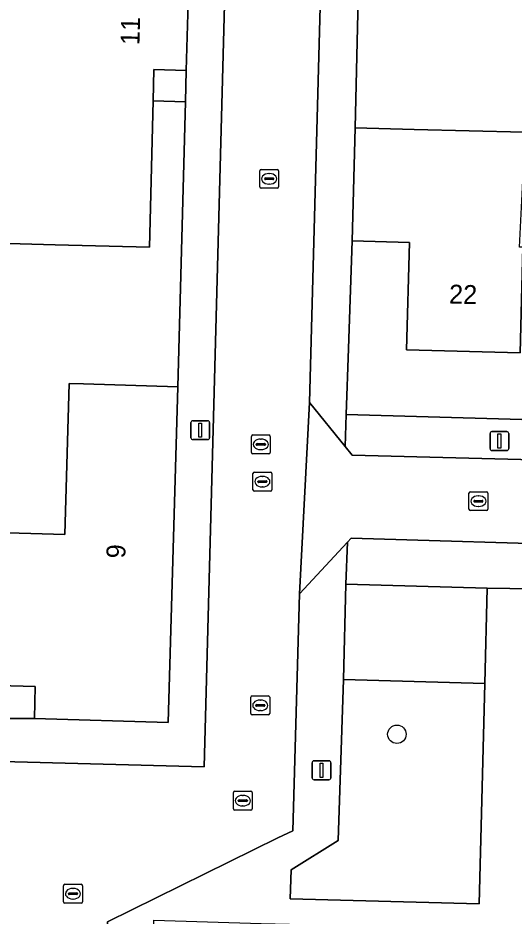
# Model space of a CAD drawing. Extents: x 162082 to 163401, y 388089 to 388636.
# Drawn here: x 162269.46 to 162295.76, y 388373.48 to 388421.05 of the extents above; entities that cross this region are included whole.
import ezdxf

# ---------------------------------------------------------------- set-up
doc = ezdxf.new("R2010")
doc.units = 0
for name, color, linetype in [('IMGEO_Boom', 7, 'Continuous'), ('IMGEO_Erf', 7, 'Continuous'), ('IMGEO_Groenvoorziening', 7, 'Continuous'), ('IMGEO_Kolk', 7, 'Continuous'), ('IMGEO_Lichtmast', 7, 'Continuous'), ('IMGEO_Pand', 7, 'Continuous'), ('IMGEO_Pand_nummerreeks', 7, 'Continuous'), ('IMGEO_Parkeervlak_open', 7, 'Continuous'), ('IMGEO_Rijbaan_lokaal_open', 7, 'Continuous'), ('IMGEO_Rioolput', 7, 'Continuous'), ('IMGEO_Voetpad_open', 7, 'Continuous')]:
    doc.layers.add(name, color=color, linetype=linetype)

msp = doc.modelspace()

# ---------------------------------------------------------------- linework, layer by layer
at = {"layer": 'IMGEO_Boom'}
msp.add_circle((162289.548, 388383.111), 0.489, dxfattribs=at)
at = {"layer": 'IMGEO_Erf'}
for points in [[(162287.643, 388428.151), (162287.33, 388415.23), (162290.47, 388415.14), (162296.3, 388415), (162297.486, 388414.97), (162297.611, 388419.901), (162301.828, 388419.797), (162301.707, 388414.866), (162305.28, 388414.78), (162308.45, 388414.69), (162311.006, 388414.617), (162310.977, 388413.354), (162314.276, 388413.279), (162314.31, 388414.54), (162317.45, 388414.47), (162320.224, 388414.408), (162320.248, 388415.309), (162325.201, 388415.178)], [(162253.993, 388382.021), (162263.305, 388381.825), (162267.927, 388381.678), (162268.022, 388383.955), (162270.33, 388383.95), (162270.37, 388385.65), (162262.65, 388385.85), (162262.792, 388390.848), (162262.88, 388393.95), (162271.95, 388393.69), (162272.18, 388401.69), (162272.933, 388401.666), (162277.93, 388401.51), (162278.34, 388416.62), (162276.63, 388416.66), (162276.44, 388408.91), (162271.442, 388409.039), (162268.32, 388409.12), (162268.59, 388418.19)], [(162325.004, 388407.681), (162323.204, 388407.728), (162323.07, 388402.63), (162317.02, 388402.78), (162317.18, 388408.45), (162314.24, 388408.54), (162314.08, 388402.86), (162313.92, 388402.87), (162308.04, 388403.01), (162308.2, 388408.71), (162305.25, 388408.79), (162305.09, 388403.086), (162298.99, 388403.24), (162299.12, 388408.84), (162296.23, 388408.91), (162296.09, 388403.316), (162290.05, 388403.47), (162290.22, 388409.16), (162287.17, 388409.25), (162286.981, 388403.548), (162286.865, 388400.044), (162322.87, 388399.024), (162324.944, 388398.956)]]:
    msp.add_lwpolyline(points, dxfattribs=at)
msp.add_lwpolyline([(162278.384, 388418.274), (162276.671, 388418.32), (162276.63, 388416.66), (162278.34, 388416.62)], close=True, dxfattribs=at)
at = {"layer": 'IMGEO_Groenvoorziening'}
msp.add_lwpolyline([(162286.712, 388386.006), (162286.434, 388377.492), (162283.941, 388375.937), (162283.893, 388374.397), (162293.903, 388374.131), (162294.211, 388385.803)], close=True, dxfattribs=at)
at = {"layer": 'IMGEO_Kolk'}
for p, q in [((162282.28, 388412.109), (162282.28, 388412.961)), ((162282.355, 388413.035), (162283.207, 388413.035)), ((162282.768, 388412.815), (162282.793, 388412.815)), ((162283.281, 388412.961), (162283.281, 388412.109)), ((162282.539, 388412.529), (162282.539, 388412.541)), ((162282.977, 388412.492), (162282.579, 388412.492)), ((162282.582, 388412.578), (162282.98, 388412.578)), ((162283.023, 388412.541), (162283.023, 388412.529)), ((162283.207, 388412.035), (162282.355, 388412.035)), ((162282.791, 388412.255), (162282.766, 388412.255)), ((162281.835, 388398.041), (162281.835, 388398.893)), ((162281.91, 388398.967), (162282.762, 388398.967)), ((162282.323, 388398.747), (162282.348, 388398.747)), ((162282.836, 388398.893), (162282.836, 388398.041)), ((162282.094, 388398.461), (162282.094, 388398.473)), ((162282.532, 388398.424), (162282.134, 388398.424)), ((162282.137, 388398.51), (162282.535, 388398.51)), ((162282.346, 388398.187), (162282.321, 388398.187)), ((162282.578, 388398.473), (162282.578, 388398.461)), ((162282.762, 388397.967), (162281.91, 388397.967)), ((162293.371, 388395.031), (162293.371, 388395.883)), ((162293.446, 388395.957), (162294.298, 388395.957)), ((162293.859, 388395.737), (162293.884, 388395.737)), ((162294.372, 388395.883), (162294.372, 388395.031)), ((162293.63, 388395.451), (162293.63, 388395.463)), ((162294.068, 388395.414), (162293.67, 388395.414)), ((162293.673, 388395.5), (162294.071, 388395.5)), ((162294.114, 388395.463), (162294.114, 388395.451)), ((162294.298, 388394.957), (162293.446, 388394.957)), ((162293.882, 388395.177), (162293.857, 388395.177)), ((162280.879, 388379.168), (162280.879, 388380.02)), ((162280.954, 388380.094), (162281.806, 388380.094)), ((162281.88, 388380.02), (162281.88, 388379.168)), ((162281.138, 388379.588), (162281.138, 388379.6)), ((162281.576, 388379.551), (162281.178, 388379.551)), ((162281.181, 388379.637), (162281.579, 388379.637)), ((162281.367, 388379.874), (162281.392, 388379.874)), ((162281.622, 388379.6), (162281.622, 388379.588)), ((162281.806, 388379.094), (162280.954, 388379.094)), ((162281.39, 388379.314), (162281.365, 388379.314))]:
    msp.add_line(p, q, dxfattribs=at)
for points in [[(162282.28, 388412.109), (162282.28, 388412.961)], [(162282.355, 388413.035), (162283.207, 388413.035)], [(162283.281, 388412.961), (162283.281, 388412.109)], [(162283.207, 388412.035), (162282.355, 388412.035)], [(162281.835, 388398.041), (162281.835, 388398.893)], [(162281.91, 388398.967), (162282.762, 388398.967)], [(162282.836, 388398.893), (162282.836, 388398.041)], [(162282.762, 388397.967), (162281.91, 388397.967)], [(162293.371, 388395.031), (162293.371, 388395.883)], [(162293.446, 388395.957), (162294.298, 388395.957)], [(162294.372, 388395.883), (162294.372, 388395.031)], [(162294.298, 388394.957), (162293.446, 388394.957)], [(162280.879, 388379.168), (162280.879, 388380.02)], [(162280.954, 388380.094), (162281.806, 388380.094)], [(162281.88, 388380.02), (162281.88, 388379.168)], [(162281.806, 388379.094), (162280.954, 388379.094)]]:
    msp.add_lwpolyline(points, dxfattribs=at)
for centre, radius, start, end in [((162282.357, 388412.959), 0.0765, 91.552, 178.448), ((162282.357, 388412.959), 0.0765, 91.552, 178.448), ((162283.205, 388412.959), 0.0765, 1.552, 88.448), ((162283.205, 388412.959), 0.0765, 1.552, 88.448), ((162282.579, 388412.538), 0.0403, 85.8775, 175.7526), ((162282.576, 388412.528), 0.0366, 178.938, 274.7102), ((162282.98, 388412.535), 0.043, 264.8664, 352.4533), ((162282.984, 388412.54), 0.0386, 1.7309, 96.639), ((162282.357, 388412.111), 0.0765, 181.552, 268.448), ((162282.357, 388412.111), 0.0765, 181.552, 268.448), ((162283.205, 388412.111), 0.0765, 271.552, 358.448), ((162283.205, 388412.111), 0.0765, 271.552, 358.448), ((162281.912, 388398.891), 0.0765, 91.552, 178.448), ((162281.912, 388398.891), 0.0765, 91.552, 178.448), ((162282.76, 388398.891), 0.0765, 1.552, 88.448), ((162282.76, 388398.891), 0.0765, 1.552, 88.448), ((162281.912, 388398.043), 0.0765, 181.552, 268.448), ((162281.912, 388398.043), 0.0765, 181.552, 268.448), ((162282.134, 388398.47), 0.0403, 85.8775, 175.7526), ((162282.131, 388398.46), 0.0366, 178.938, 274.7102), ((162282.535, 388398.467), 0.043, 264.8664, 352.4533), ((162282.539, 388398.472), 0.0386, 1.7309, 96.639), ((162282.76, 388398.043), 0.0765, 271.552, 358.448), ((162282.76, 388398.043), 0.0765, 271.552, 358.448), ((162293.448, 388395.881), 0.0765, 91.552, 178.448), ((162293.448, 388395.881), 0.0765, 91.552, 178.448), ((162294.296, 388395.881), 0.0765, 1.552, 88.448), ((162294.296, 388395.881), 0.0765, 1.552, 88.448), ((162293.67, 388395.46), 0.0403, 85.8775, 175.7526), ((162293.667, 388395.45), 0.0366, 178.938, 274.7102), ((162294.071, 388395.457), 0.043, 264.8664, 352.4533), ((162294.075, 388395.462), 0.0386, 1.7309, 96.639), ((162293.448, 388395.033), 0.0765, 181.552, 268.448), ((162293.448, 388395.033), 0.0765, 181.552, 268.448), ((162294.296, 388395.033), 0.0765, 271.552, 358.448), ((162294.296, 388395.033), 0.0765, 271.552, 358.448), ((162280.956, 388380.018), 0.0765, 91.552, 178.448), ((162280.956, 388380.018), 0.0765, 91.552, 178.448), ((162281.804, 388380.018), 0.0765, 1.552, 88.448), ((162281.804, 388380.018), 0.0765, 1.552, 88.448), ((162281.178, 388379.597), 0.0403, 85.8775, 175.7526), ((162281.175, 388379.587), 0.0366, 178.938, 274.7102), ((162281.579, 388379.594), 0.043, 264.8664, 352.4533), ((162281.583, 388379.599), 0.0386, 1.7309, 96.639), ((162280.956, 388379.17), 0.0765, 181.552, 268.448), ((162280.956, 388379.17), 0.0765, 181.552, 268.448), ((162281.804, 388379.17), 0.0765, 271.552, 358.448), ((162281.804, 388379.17), 0.0765, 271.552, 358.448)]:
    msp.add_arc(centre, radius, start, end, dxfattribs=at)
for centre, major_axis, ratio, start_param, end_param in [((162282.767, 388412.535), (-0.387, 0.002), 0.722429, 4.712389, 7.853982), ((162282.792, 388412.535), (-0.39, 0.002), 0.717154, 1.570796, 4.712389), ((162282.322, 388398.467), (-0.387, 0.002), 0.722429, 4.712389, 7.853982), ((162282.347, 388398.467), (-0.39, 0.002), 0.717154, 1.570796, 4.712389), ((162293.858, 388395.457), (-0.387, 0.002), 0.722429, 4.712389, 7.853982), ((162293.883, 388395.457), (-0.39, 0.002), 0.717154, 1.570796, 4.712389), ((162281.366, 388379.594), (-0.387, 0.002), 0.722429, 4.712389, 7.853982), ((162281.391, 388379.594), (-0.39, 0.002), 0.717154, 1.570796, 4.712389)]:
    msp.add_ellipse(centre, major_axis=major_axis, ratio=ratio, start_param=start_param, end_param=end_param, dxfattribs=at)
at = {"layer": 'IMGEO_Lichtmast'}
for p, q in [((162278.628, 388398.821), (162278.628, 388399.621)), ((162278.628, 388399.621), (162278.628, 388398.821)), ((162278.728, 388399.721), (162279.518, 388399.721)), ((162279.518, 388399.721), (162278.728, 388399.721)), ((162279.618, 388399.621), (162279.618, 388398.821)), ((162279.618, 388398.821), (162279.618, 388399.621)), ((162294.489, 388398.242), (162294.489, 388399.042)), ((162294.489, 388399.042), (162294.489, 388398.242)), ((162294.589, 388399.142), (162295.379, 388399.142)), ((162295.379, 388399.142), (162294.589, 388399.142)), ((162295.479, 388399.042), (162295.479, 388398.242)), ((162295.479, 388398.242), (162295.479, 388399.042)), ((162279.518, 388398.721), (162278.728, 388398.721)), ((162278.728, 388398.721), (162279.518, 388398.721)), ((162295.379, 388398.142), (162294.589, 388398.142)), ((162294.589, 388398.142), (162295.379, 388398.142)), ((162285.058, 388380.805), (162285.058, 388381.605)), ((162285.058, 388381.605), (162285.058, 388380.805)), ((162285.158, 388381.705), (162285.948, 388381.705)), ((162285.948, 388381.705), (162285.158, 388381.705)), ((162286.048, 388381.605), (162286.048, 388380.805)), ((162286.048, 388380.805), (162286.048, 388381.605)), ((162285.948, 388380.705), (162285.158, 388380.705)), ((162285.158, 388380.705), (162285.948, 388380.705))]:
    msp.add_line(p, q, dxfattribs=at)
for points in [[(162279.048, 388399.596), (162279.198, 388399.596), (162279.198, 388398.846), (162279.048, 388398.846), (162279.048, 388399.596)], [(162294.909, 388399.017), (162295.059, 388399.017), (162295.059, 388398.267), (162294.909, 388398.267), (162294.909, 388399.017)], [(162285.478, 388381.58), (162285.628, 388381.58), (162285.628, 388380.83), (162285.478, 388380.83), (162285.478, 388381.58)]]:
    msp.add_lwpolyline(points, dxfattribs=at)
for centre, start, end in [((162278.728, 388399.621), 90, 180), ((162278.728, 388399.621), 90, 180), ((162279.518, 388399.621), 0, 90), ((162279.518, 388399.621), 360, 90), ((162294.589, 388399.042), 90, 180), ((162294.589, 388399.042), 90, 180), ((162295.379, 388399.042), 0, 90), ((162295.379, 388399.042), 360, 90), ((162278.728, 388398.821), 180, 270), ((162278.728, 388398.821), 180, 270), ((162279.518, 388398.821), 270, 0), ((162279.518, 388398.821), 270, 0), ((162294.589, 388398.242), 180, 270), ((162294.589, 388398.242), 180, 270), ((162295.379, 388398.242), 270, 0), ((162295.379, 388398.242), 270, 0), ((162285.158, 388381.605), 90, 180), ((162285.158, 388381.605), 90, 180), ((162285.948, 388381.605), 0, 90), ((162285.948, 388381.605), 360, 90), ((162285.158, 388380.805), 180, 270), ((162285.158, 388380.805), 180, 270), ((162285.948, 388380.805), 270, 0), ((162285.948, 388380.805), 270, 0)]:
    msp.add_arc(centre, 0.1, start, end, dxfattribs=at)
at = {"layer": 'IMGEO_Pand'}
for points in [[(162276.671, 388418.32), (162278.384, 388418.274), (162278.53, 388423.7), (162268.45, 388423.983), (162266.435, 388424.04), (162260.75, 388424.2), (162260.74, 388423.862), (162249.178, 388424.187), (162249.948, 388420.117), (162256.261, 388419.94), (162256.246, 388419.402), (162260.605, 388419.28), (162260.603, 388419.203), (162260.58, 388418.43), (162268.59, 388418.19), (162268.32, 388409.12), (162271.442, 388409.039), (162276.44, 388408.91), (162276.63, 388416.66)], [(162296.23, 388408.91), (162296.041, 388408.915), (162296.25, 388412.799), (162296.3, 388415), (162290.47, 388415.14), (162287.33, 388415.23), (162287.17, 388409.25), (162290.22, 388409.16), (162290.05, 388403.47), (162296.09, 388403.316)], [(162270.33, 388383.95), (162277.42, 388383.73), (162277.93, 388401.51), (162272.933, 388401.666), (162272.18, 388401.69), (162271.95, 388393.69), (162262.88, 388393.95), (162262.792, 388390.848), (162262.65, 388385.85), (162270.37, 388385.65)]]:
    msp.add_lwpolyline(points, close=True, dxfattribs=at)
at = {"layer": 'IMGEO_Parkeervlak_open'}
msp.add_lwpolyline([(162286.712, 388386.006), (162294.211, 388385.803), (162294.332, 388390.848), (162286.847, 388391.062)], close=True, dxfattribs=at)
at = {"layer": 'IMGEO_Rijbaan_lokaal_open'}
for points in [[(162284.925, 388400.688), (162285.665, 388428.206), (162282.526, 388428.289), (162275.672, 388432.618), (162275.709, 388433.959), (162277.281, 388490.305), (162281.271, 388493.758), (162282.872, 388495.185), (162282.421, 388500.795), (162280.034, 388500), (162272.542, 388497.504), (162270.706, 388434.142), (162270.583, 388429.903), (162280.46, 388423.762), (162279.34, 388381.38), (162267.927, 388381.678), (162267.422, 388364.914), (162273.985, 388364.716), (162274.2, 388373.179), (162283.239, 388377.625), (162284.037, 388377.998), (162284.394, 388390.548)], [(162300.231, 388397.566), (162287.185, 388397.891), (162286.815, 388398.348), (162284.925, 388400.688), (162284.394, 388390.548), (162286.938, 388393.289), (162287.125, 388393.491), (162300.121, 388393.114)]]:
    msp.add_lwpolyline(points, close=True, dxfattribs=at)
at = {"layer": 'IMGEO_Rioolput'}
for p, q in [((162281.919, 388396.067), (162281.919, 388396.919)), ((162281.994, 388396.993), (162282.846, 388396.993)), ((162282.407, 388396.773), (162282.432, 388396.773)), ((162282.92, 388396.919), (162282.92, 388396.067)), ((162282.178, 388396.487), (162282.178, 388396.499)), ((162282.616, 388396.45), (162282.218, 388396.45)), ((162282.221, 388396.536), (162282.619, 388396.536)), ((162282.43, 388396.213), (162282.405, 388396.213)), ((162282.662, 388396.499), (162282.662, 388396.487)), ((162282.846, 388395.993), (162281.994, 388395.993)), ((162281.806, 388384.216), (162281.806, 388385.068)), ((162281.881, 388385.142), (162282.733, 388385.142)), ((162282.294, 388384.922), (162282.319, 388384.922)), ((162282.807, 388385.068), (162282.807, 388384.216)), ((162282.065, 388384.636), (162282.065, 388384.648)), ((162282.503, 388384.599), (162282.105, 388384.599)), ((162282.108, 388384.685), (162282.506, 388384.685)), ((162282.317, 388384.362), (162282.292, 388384.362)), ((162282.549, 388384.648), (162282.549, 388384.636)), ((162282.733, 388384.142), (162281.881, 388384.142)), ((162271.878, 388374.239), (162271.878, 388375.091)), ((162271.953, 388375.165), (162272.805, 388375.165)), ((162272.366, 388374.945), (162272.391, 388374.945)), ((162272.879, 388375.091), (162272.879, 388374.239)), ((162272.137, 388374.659), (162272.137, 388374.671)), ((162272.575, 388374.622), (162272.177, 388374.622)), ((162272.18, 388374.708), (162272.578, 388374.708)), ((162272.389, 388374.385), (162272.364, 388374.385)), ((162272.621, 388374.671), (162272.621, 388374.659)), ((162272.805, 388374.165), (162271.953, 388374.165))]:
    msp.add_line(p, q, dxfattribs=at)
for points in [[(162281.919, 388396.067), (162281.919, 388396.919)], [(162281.994, 388396.993), (162282.846, 388396.993)], [(162282.92, 388396.919), (162282.92, 388396.067)], [(162282.846, 388395.993), (162281.994, 388395.993)], [(162281.806, 388384.216), (162281.806, 388385.068)], [(162281.881, 388385.142), (162282.733, 388385.142)], [(162282.807, 388385.068), (162282.807, 388384.216)], [(162282.733, 388384.142), (162281.881, 388384.142)], [(162271.878, 388374.239), (162271.878, 388375.091)], [(162271.953, 388375.165), (162272.805, 388375.165)], [(162272.879, 388375.091), (162272.879, 388374.239)], [(162272.805, 388374.165), (162271.953, 388374.165)]]:
    msp.add_lwpolyline(points, dxfattribs=at)
for centre, radius, start, end in [((162281.996, 388396.917), 0.0765, 91.552, 178.448), ((162281.996, 388396.917), 0.0765, 91.552, 178.448), ((162282.844, 388396.917), 0.0765, 1.552, 88.448), ((162282.844, 388396.917), 0.0765, 1.552, 88.448), ((162282.218, 388396.496), 0.0403, 85.8775, 175.7526), ((162282.215, 388396.486), 0.0366, 178.938, 274.7102), ((162282.619, 388396.493), 0.043, 264.8664, 352.4533), ((162282.623, 388396.498), 0.0386, 1.7309, 96.639), ((162281.996, 388396.069), 0.0765, 181.552, 268.448), ((162281.996, 388396.069), 0.0765, 181.552, 268.448), ((162282.844, 388396.069), 0.0765, 271.552, 358.448), ((162282.844, 388396.069), 0.0765, 271.552, 358.448), ((162281.883, 388385.066), 0.0765, 91.552, 178.448), ((162281.883, 388385.066), 0.0765, 91.552, 178.448), ((162282.731, 388385.066), 0.0765, 1.552, 88.448), ((162282.731, 388385.066), 0.0765, 1.552, 88.448), ((162282.105, 388384.645), 0.0403, 85.8775, 175.7526), ((162282.102, 388384.635), 0.0366, 178.938, 274.7102), ((162282.506, 388384.642), 0.043, 264.8664, 352.4533), ((162282.51, 388384.647), 0.0386, 1.7309, 96.639), ((162281.883, 388384.218), 0.0765, 181.552, 268.448), ((162281.883, 388384.218), 0.0765, 181.552, 268.448), ((162282.731, 388384.218), 0.0765, 271.552, 358.448), ((162282.731, 388384.218), 0.0765, 271.552, 358.448), ((162271.955, 388375.089), 0.0765, 91.552, 178.448), ((162271.955, 388375.089), 0.0765, 91.552, 178.448), ((162272.803, 388375.089), 0.0765, 1.552, 88.448), ((162272.803, 388375.089), 0.0765, 1.552, 88.448), ((162272.177, 388374.668), 0.0403, 85.8775, 175.7526), ((162272.174, 388374.658), 0.0366, 178.938, 274.7102), ((162272.578, 388374.665), 0.043, 264.8664, 352.4533), ((162272.582, 388374.67), 0.0386, 1.7309, 96.639), ((162271.955, 388374.241), 0.0765, 181.552, 268.448), ((162271.955, 388374.241), 0.0765, 181.552, 268.448), ((162272.803, 388374.241), 0.0765, 271.552, 358.448), ((162272.803, 388374.241), 0.0765, 271.552, 358.448)]:
    msp.add_arc(centre, radius, start, end, dxfattribs=at)
for centre, major_axis, ratio, start_param, end_param in [((162282.406, 388396.493), (-0.387, 0.002), 0.722429, 4.712389, 7.853982), ((162282.431, 388396.493), (-0.39, 0.002), 0.717154, 1.570796, 4.712389), ((162282.293, 388384.642), (-0.387, 0.002), 0.722429, 4.712389, 7.853982), ((162282.318, 388384.642), (-0.39, 0.002), 0.717154, 1.570796, 4.712389), ((162272.365, 388374.665), (-0.387, 0.002), 0.722429, 4.712389, 7.853982), ((162272.39, 388374.665), (-0.39, 0.002), 0.717154, 1.570796, 4.712389)]:
    msp.add_ellipse(centre, major_axis=major_axis, ratio=ratio, start_param=start_param, end_param=end_param, dxfattribs=at)
at = {"layer": 'IMGEO_Voetpad_open'}
for points in [[(162272.542, 388497.504), (162270.551, 388496.899), (162270.18, 388486.44), (162270.01, 388479.33), (162269.7, 388468.68), (162269.542, 388463.085), (162269.5, 388461.6), (162269.23, 388450.96), (162269.06, 388443.84), (162268.765, 388434.213), (162268.604, 388428.981), (162268.45, 388423.983), (162278.53, 388423.7), (162278.384, 388418.274), (162278.34, 388416.62), (162277.93, 388401.51), (162277.42, 388383.73), (162270.33, 388383.95), (162268.022, 388383.955), (162267.927, 388381.678), (162279.34, 388381.38), (162280.46, 388423.762), (162270.583, 388429.903), (162270.706, 388434.142)], [(162287.643, 388428.151), (162285.665, 388428.206), (162284.925, 388400.688), (162286.815, 388398.348), (162286.865, 388400.044), (162286.981, 388403.548), (162287.17, 388409.25), (162287.33, 388415.23)], [(162324.944, 388398.956), (162322.87, 388399.024), (162286.865, 388400.044), (162286.815, 388398.348), (162287.185, 388397.891), (162300.231, 388397.566), (162303.131, 388397.494), (162322.248, 388396.946), (162324.875, 388396.866)], [(162324.775, 388392.309), (162322.38, 388392.395), (162303.02, 388393.03), (162300.121, 388393.114), (162287.125, 388393.491), (162286.938, 388393.289), (162286.847, 388391.062), (162294.332, 388390.848), (162296.746, 388390.816), (162311.432, 388390.317), (162321.655, 388389.97), (162323.288, 388389.915), (162324.727, 388389.88)]]:
    msp.add_lwpolyline(points, close=True, dxfattribs=at)
msp.add_lwpolyline([(162274.738, 388299.666), (162276.659, 388373.258), (162282.346, 388373.091), (162283.855, 388373.048), (162290.369, 388372.882), (162296.268, 388372.715), (162296.746, 388390.816), (162294.332, 388390.848), (162294.211, 388385.803), (162293.903, 388374.131), (162283.893, 388374.397), (162283.941, 388375.937), (162286.434, 388377.492), (162286.712, 388386.006), (162286.847, 388391.062), (162286.938, 388393.289), (162284.394, 388390.548), (162284.037, 388377.998), (162283.239, 388377.625), (162274.2, 388373.179), (162273.985, 388364.716), (162273.918, 388362.117), (162271.94, 388284.429)], dxfattribs=at)

# ---------------------------------------------------------------- texts
at = {"layer": 'IMGEO_Pand_nummerreeks'}
for s, rotation, p in [('11', 88.4647, (162275.899, 388419.607)), ('22', 358.5395, (162292.305, 388405.933)), ('9', 88.357, (162275.148, 388392.417))]:
    msp.add_text(s, height=1, rotation=rotation, dxfattribs=at).set_placement(p)

doc.saveas('drawing.dxf')
